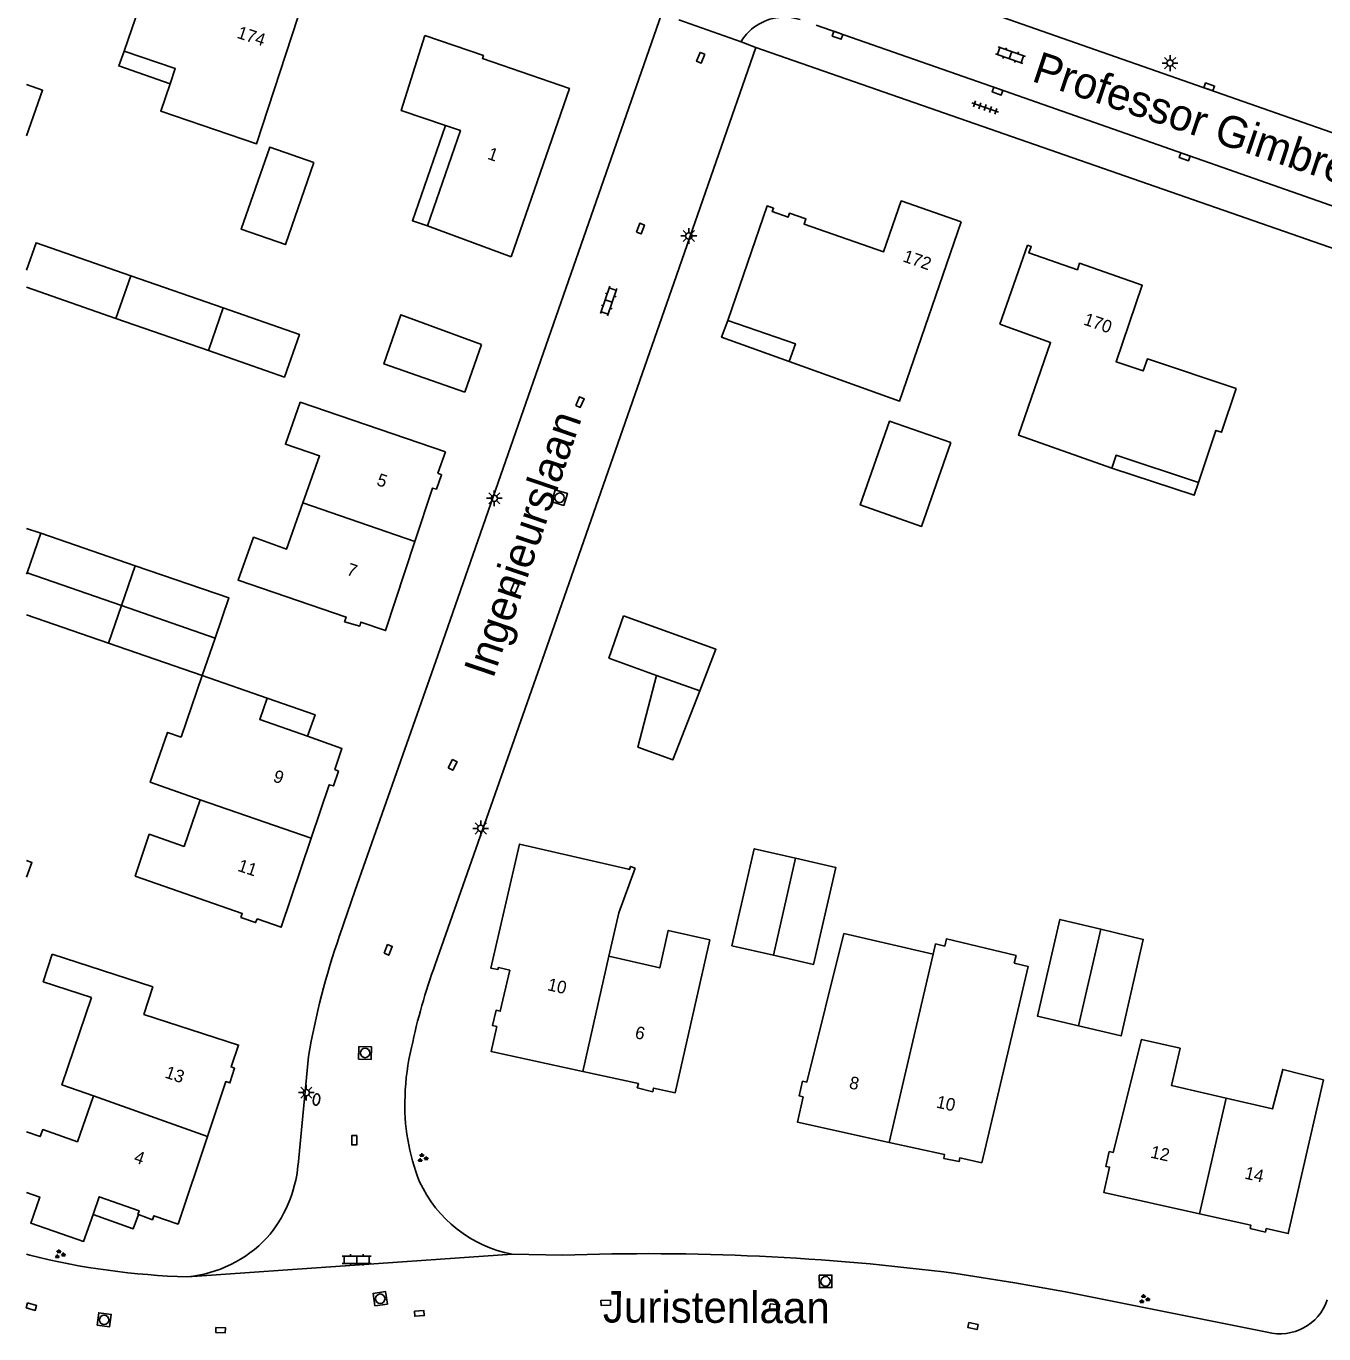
# Model space of a CAD drawing. Extents: x 131000 to 133014, y 396499 to 399001.
# Drawn here: x 131000 to 131103.1, y 396804.1 to 396908.1 of the extents above; entities that cross this region are included whole.
import ezdxf

# ---------------------------------------------------------------- set-up
doc = ezdxf.new("R2010")
doc.units = 0
for name, color, linetype in [('gg-anno-huisnummerreeks BGT', 7, 'Continuous'), ('gg-anno-openbare ruimte label', 7, 'Continuous'), ('gg-bbg-bijgebouw', 7, 'Continuous'), ('gg-bbg-gedigitaliseerde bebouwing', 7, 'Continuous'), ('gg-bbg-gedigitaliseerde bijgebouw', 7, 'Continuous'), ('gg-bbg-hoofdgebouw', 7, 'Continuous'), ('gg-bbg-luifel en loopbrug', 7, 'Continuous'), ('gg-bbg-tussenscheiding', 7, 'Continuous'), ('gg-knt-verharding', 7, 'Continuous'), ('gt-grn-weggrens', 7, 'Continuous'), ('gt-symb-brandkraan', 7, 'Continuous'), ('gt-symb-groenvak', 7, 'Continuous'), ('gt-symb-klinker verharding', 7, 'Continuous'), ('gt-symb-kolk', 7, 'Continuous'), ('gt-symb-kolk center center', 7, 'Continuous'), ('gt-symb-lichtmast', 7, 'Continuous'), ('gt-symb-rioolschacht', 7, 'Continuous'), ('gt-symb-tegel verharding', 7, 'Continuous')]:
    doc.layers.add(name, color=color, linetype=linetype)

# ---------------------------------------------------------------- blocks, each defined once
blk = doc.blocks.new('gt0-KOLK')
at = {"layer": 'gt-symb-kolk'}
blk.add_lwpolyline([(0, 0), (0.38, 0), (0.38, 0.4), (-0.38, 0.4), (-0.38, 0), (0, 0)], dxfattribs=at)
blk = doc.blocks.new('gt0-TEG1')
at = {"layer": 'gt-symb-tegel verharding'}
for p, q in [((-1.12, 0), (1.12, 0)), ((-0.9, -0.25), (-0.9, 0.25)), ((-0.45, -0.25), (-0.45, 0.25)), ((0, -0.25), (0, 0.25)), ((0.45, -0.25), (0.45, 0.25)), ((0.9, -0.25), (0.9, 0.25))]:
    blk.add_line(p, q, dxfattribs=at)
blk = doc.blocks.new('gt0-LMAST')
at = {"layer": 'gt-symb-lichtmast'}
for p, q in [((-0.18, 0.17), (-0.45, 0.44)), ((-0.01, 0.25), (-0.01, 0.62)), ((0.17, 0.17), (0.44, 0.44)), ((-0.26, 0), (-0.63, 0)), ((-0.18, -0.18), (-0.45, -0.45)), ((-0.01, -0.25), (-0.01, -0.63)), ((0.44, -0.45), (0.17, -0.18)), ((0.24, 0), (0.62, 0))]:
    blk.add_line(p, q, dxfattribs=at)
blk.add_circle((-0.01, 0), 0.25, dxfattribs=at)
blk = doc.blocks.new('gt0-KL1')
at = {"layer": 'gt-symb-klinker verharding'}
for p, q in [((-1.15, 0.3), (1.15, 0.3)), ((-1, -0.3), (-1, 0.3)), ((-0.5, 0.3), (-0.5, 0.45)), ((0, -0.3), (0, 0.3)), ((0.5, 0.3), (0.5, 0.45)), ((1, -0.3), (1, 0.3)), ((-1.15, -0.3), (1.15, -0.3)), ((-0.5, -0.45), (-0.5, -0.3)), ((0.5, -0.45), (0.5, -0.3))]:
    blk.add_line(p, q, dxfattribs=at)
blk = doc.blocks.new('gt0-KOLKCC')
at = {"layer": 'gt-symb-kolk center center'}
blk.add_lwpolyline([(-0.37, 0.2), (0.38, 0.2), (0.38, -0.2), (-0.37, -0.2)], close=True, dxfattribs=at)
blk = doc.blocks.new('gt0-RS')
at = {"layer": 'gt-symb-rioolschacht'}
blk.add_lwpolyline([(-0.5, -0.5), (0.5, -0.5), (0.5, 0.5), (-0.5, 0.5)], close=True, dxfattribs=at)
blk.add_circle((0, 0), 0.375, dxfattribs=at)
blk = doc.blocks.new('gt0-GRVAK')
at = {"layer": 'gt-symb-groenvak'}
for p, q in [((-0.11, 0.19), (-0.23, 0.24)), ((-0.18, 0.15), (0.09, 0.15)), ((-0.09, 0.21), (-0.16, 0.32)), ((-0.05, 0.21), (-0.05, 0.39)), ((0, 0.21), (0.06, 0.32)), ((0.02, 0.19), (0.13, 0.24)), ((0.26, -0.05), (0.2, 0.06)), ((0.3, -0.05), (0.3, 0.13)), ((0.35, -0.05), (0.41, 0.06)), ((-0.24, -0.23), (-0.36, -0.18)), ((-0.32, -0.26), (-0.05, -0.26)), ((-0.23, -0.21), (-0.29, -0.09)), ((-0.18, -0.2), (-0.18, -0.02)), ((-0.14, -0.21), (-0.07, -0.09)), ((-0.12, -0.23), (0, -0.18)), ((0.24, -0.07), (0.12, -0.02)), ((0.17, -0.11), (0.44, -0.11)), ((0.37, -0.07), (0.49, -0.02))]:
    blk.add_line(p, q, dxfattribs=at)
blk = doc.blocks.new('gt0-BR')
at = {"layer": 'gt-symb-brandkraan'}
for centre, radius, start, end in [((-0.24, 0), 0.206, 107.5669, 252.4331), ((0.6, -2.66), 3, 106.892, 107.5669), ((0, -0.69), 0.938, 73.108, 106.892), ((-0.6, -2.66), 3, 72.4331, 73.108), ((0.24, 0), 0.206, 287.567, 72.4331), ((0.6, 2.66), 3, 252.4331, 253.108), ((0, 0.69), 0.938, 253.108, 286.8921), ((-0.6, 2.66), 3, 286.8921, 287.567)]:
    blk.add_arc(centre, radius, start, end, dxfattribs=at)

msp = doc.modelspace()

# ---------------------------------------------------------------- linework, layer by layer
at = {"layer": 'gg-bbg-bijgebouw'}
for p, q in [((131036.15, 396882.77), (131034.81, 396879)), ((131047.42, 396861.2), (131046.26, 396857.84))]:
    msp.add_line(p, q, dxfattribs=at)
at = {"layer": 'gg-bbg-gedigitaliseerde bebouwing'}
for p, q in [((131007.74, 396906.1), (131010.7, 396914.65)), ((131038.5, 396889.73), (131031.84, 396892.2)), ((131077.32, 396884.39), (131079.51, 396890.68)), ((131013.95, 396856.47), (131012.27, 396851.58)), ((131075.9, 396817.74), (131078.76, 396829.85)), ((131005.29, 396822.99), (131005.31, 396823.06))]:
    msp.add_line(p, q, dxfattribs=at)
for points in [[(131022.01, 396910.13), (131018.27, 396898.73), (131010.66, 396901.33), (131011.4, 396903.49)], [(131033.27, 396900.19), (131029.76, 396901.36), (131031.64, 396907.33)], [(131011.4, 396903.49), (131011.81, 396904.7), (131007.74, 396906.1)], [(131031.84, 396892.2), (131034.46, 396899.79), (131033.27, 396900.19)], [(131074.24, 396892.53), (131069.36, 396878.28), (131060.59, 396881.42)], [(131086.23, 396872.95), (131078.79, 396875.57), (131081.35, 396882.94), (131077.32, 396884.39)], [(131096.1, 396879.27), (131094.93, 396875.8), (131094.48, 396875.95), (131093.1, 396871.82)], [(131021.96, 396870.2), (131023.28, 396873.92), (131020.56, 396874.85), (131021.74, 396878.18), (131033.27, 396874.24)], [(131093.1, 396871.82), (131086.56, 396873.97), (131086.23, 396872.95)], [(131021.96, 396870.2), (131020.66, 396866.51), (131018.03, 396867.45), (131016.8, 396864.05), (131025.38, 396861.11), (131025.27, 396860.73)], [(131013.8, 396846.6), (131009.82, 396847.98), (131011.2, 396851.95), (131012.27, 396851.58)], [(131013.8, 396846.6), (131012.51, 396842.89), (131009.75, 396843.85), (131008.63, 396840.53), (131017.14, 396837.55), (131017.03, 396837.24)], [(131046.25, 396834.16), (131047.04, 396837.62), (131048.34, 396841.17)], [(131051.54, 396823.31), (131054.27, 396835.46), (131050.98, 396836.21), (131050.3, 396833.23), (131046.25, 396834.16)], [(131072.02, 396834.32), (131064.93, 396835.96), (131061.98, 396824.15), (131061.65, 396824.23)], [(131078.76, 396829.85), (131079.58, 396833.34), (131078.46, 396833.61), (131078.61, 396834.22), (131073.08, 396835.53), (131072.94, 396834.97), (131072.21, 396835.14), (131072.02, 396834.32)], [(131005.16, 396830.89), (131001.33, 396832.13), (131002.04, 396834.32)], [(131005.16, 396830.89), (131002.81, 396823.95), (131005.31, 396823.06)], [(131095.29, 396822.88), (131090.96, 396823.88), (131091.64, 396826.84), (131088.57, 396827.53), (131086.33, 396818.56), (131086.01, 396818.64)], [(131103.02, 396824.33), (131099.79, 396825.16), (131098.98, 396822.02), (131095.29, 396822.88)]]:
    msp.add_lwpolyline(points, dxfattribs=at)
at = {"layer": 'gg-bbg-gedigitaliseerde bijgebouw'}
for p, q in [((131008.29, 396888.23), (131015.62, 396885.68)), ((131000, 396887.32), (131007.1, 396884.85)), ((131014.44, 396882.29), (131015.62, 396885.68)), ((131014.44, 396882.29), (131007.1, 396884.85)), ((131000, 396868.16), (131001.14, 396867.77)), ((131001.14, 396867.77), (131008.62, 396865.19)), ((131007.53, 396862.02), (131008.62, 396865.19)), ((131000, 396861.28), (131006.51, 396859.04)), ((131006.51, 396859.04), (131007.53, 396862.02)), ((131050.04, 396856.48), (131046.26, 396857.84)), ((131053.49, 396855.24), (131050.04, 396856.48))]:
    msp.add_line(p, q, dxfattribs=at)
for points in [[(131000, 396903.43), (131001.27, 396902.98), (131000, 396899.37)], [(131022.83, 396897.25), (131019.33, 396898.46), (131017.06, 396891.93), (131020.56, 396890.72), (131022.83, 396897.25)], [(131000, 396888.69), (131000.76, 396890.86), (131008.29, 396888.23)], [(131034.81, 396879), (131028.39, 396881.23), (131029.74, 396885.14), (131036.15, 396882.77)], [(131073.42, 396874.98), (131068.55, 396876.68), (131066.23, 396870.02), (131071.1, 396868.32), (131073.42, 396874.98)], [(131047.42, 396861.2), (131054.76, 396858.56), (131053.49, 396855.24)], [(131061.09, 396841.95), (131057.81, 396842.7), (131056.04, 396834.99), (131059.35, 396834.23)], [(131000, 396841.76), (131000.42, 396841.61), (131000, 396840.43)], [(131059.35, 396834.23), (131062.52, 396833.51), (131064.28, 396841.22), (131061.09, 396841.95)], [(131085.34, 396836.3), (131082.09, 396837.09), (131080.32, 396829.39), (131083.56, 396828.62)], [(131083.56, 396828.62), (131086.95, 396827.82), (131088.72, 396835.49), (131085.34, 396836.3)]]:
    msp.add_lwpolyline(points, dxfattribs=at)
at = {"layer": 'gg-bbg-hoofdgebouw'}
msp.add_line((131013.95, 396856.47), (131019.12, 396854.67), dxfattribs=at)
for points in [[(131038.5, 396889.73), (131043.12, 396903.13), (131036.22, 396905.51), (131036.3, 396905.74), (131031.64, 396907.33)], [(131074.24, 396892.53), (131069.49, 396894.18), (131068.09, 396890.14), (131061.77, 396892.34), (131061.92, 396892.75), (131060.61, 396893.2), (131060.51, 396892.9), (131059.24, 396893.34), (131059.34, 396893.61), (131058.83, 396893.79), (131055.7, 396884.69)], [(131096.1, 396879.27), (131089.04, 396881.63), (131088.7, 396880.67), (131086.55, 396881.41), (131088.64, 396887.49), (131083.66, 396889.23), (131083.48, 396888.72), (131079.63, 396890.06), (131079.81, 396890.57), (131079.51, 396890.68)], [(131055.7, 396884.69), (131061.08, 396882.84), (131060.59, 396881.42)], [(131030.84, 396867.11), (131032.24, 396871.37), (131032.56, 396871.28), (131032.97, 396872.43), (131032.68, 396872.55), (131033.27, 396874.24)], [(131025.27, 396860.73), (131026.47, 396860.4), (131026.55, 396860.71), (131028.52, 396860.04), (131030.84, 396867.11)], [(131019.12, 396854.67), (131018.52, 396852.97), (131022.32, 396851.64)], [(131022.32, 396851.64), (131025.05, 396850.68), (131024.49, 396848.99), (131024.78, 396848.86), (131024.38, 396847.69), (131024.04, 396847.79), (131022.61, 396843.55)], [(131017.03, 396837.24), (131018.19, 396836.83), (131018.32, 396837.13), (131020.23, 396836.46), (131022.61, 396843.55)], [(131044.19, 396825), (131036.9, 396826.59), (131037.35, 396828.57), (131037.01, 396828.65), (131037.3, 396829.87), (131037.63, 396829.79), (131038.38, 396833.05), (131037.48, 396833.26), (131037.44, 396833.11), (131036.88, 396833.22), (131039.17, 396843.07), (131047.82, 396841.08)], [(131048.34, 396841.17), (131047.97, 396841.3), (131047.91, 396841.06), (131047.82, 396841.08)], [(131002.04, 396834.32), (131010.03, 396831.72), (131009.32, 396829.54), (131016.84, 396827.09), (131016.25, 396825.36), (131016.53, 396825.25), (131016.15, 396824.09), (131015.83, 396824.19), (131014.37, 396819.83)], [(131051.54, 396823.31), (131049.81, 396823.68), (131049.74, 396823.39), (131048.52, 396823.7), (131048.61, 396824.04), (131044.19, 396825)], [(131068.54, 396819.36), (131061.24, 396820.98), (131061.69, 396822.98), (131061.38, 396823.05), (131061.65, 396824.23)], [(131103.02, 396824.33), (131100.23, 396812.11), (131098.48, 396812.51), (131098.42, 396812.24), (131097.21, 396812.52), (131097.27, 396812.78), (131093.19, 396813.69)], [(131000, 396820.21), (131001.09, 396819.83), (131001.28, 396820.38), (131004.04, 396819.42), (131005.29, 396822.99)], [(131014.37, 396819.83), (131012.03, 396812.87), (131010.1, 396813.53), (131010, 396813.22), (131008.88, 396813.62)], [(131075.9, 396817.74), (131074.14, 396818.13), (131074.08, 396817.84), (131072.86, 396818.09), (131072.93, 396818.39), (131068.54, 396819.36)], [(131093.19, 396813.69), (131085.59, 396815.38), (131086.04, 396817.39), (131085.73, 396817.46), (131086.01, 396818.64)], [(131000, 396815.37), (131001.05, 396815.01), (131000.33, 396812.95), (131004.53, 396811.49), (131005.28, 396813.62)], [(131005.28, 396813.62), (131005.77, 396815.04), (131008.94, 396813.93), (131008.84, 396813.63), (131008.88, 396813.62)]]:
    msp.add_lwpolyline(points, dxfattribs=at)
at = {"layer": 'gg-bbg-luifel en loopbrug'}
for p, q in [((131007.53, 396862.02), (131014.97, 396859.43)), ((131013.95, 396856.47), (131014.97, 396859.43)), ((131006.51, 396859.04), (131013.95, 396856.47))]:
    msp.add_line(p, q, dxfattribs=at)
for points in [[(131007.74, 396906.1), (131007.32, 396904.91), (131011.4, 396903.49)], [(131031.84, 396892.2), (131030.65, 396892.61), (131033.27, 396900.19)], [(131015.62, 396885.68), (131021.67, 396883.57), (131020.49, 396880.19), (131014.44, 396882.29)], [(131055.7, 396884.69), (131055.22, 396883.35), (131060.59, 396881.42)], [(131086.23, 396872.95), (131092.76, 396870.8), (131093.1, 396871.82)], [(131008.62, 396865.19), (131016.07, 396862.63), (131014.97, 396859.43)], [(131053.49, 396855.24), (131051.35, 396849.77), (131048.57, 396850.77), (131050.04, 396856.48)], [(131019.12, 396854.67), (131022.92, 396853.35), (131022.32, 396851.64)], [(131005.28, 396813.62), (131008.48, 396812.5), (131008.88, 396813.62)]]:
    msp.add_lwpolyline(points, dxfattribs=at)
at = {"layer": 'gg-bbg-tussenscheiding'}
for p, q in [((131007.1, 396884.85), (131008.29, 396888.23)), ((131030.84, 396867.11), (131021.96, 396870.2)), ((131000.04, 396864.63), (131001.14, 396867.77)), ((131000, 396864.65), (131000.04, 396864.63)), ((131000, 396864.51), (131000.04, 396864.63)), ((131000.04, 396864.63), (131007.53, 396862.02)), ((131022.61, 396843.55), (131013.8, 396846.6)), ((131061.09, 396841.95), (131059.35, 396834.23)), ((131085.34, 396836.3), (131083.56, 396828.62)), ((131046.25, 396834.16), (131044.19, 396825)), ((131072.02, 396834.32), (131068.54, 396819.36)), ((131005.31, 396823.06), (131014.37, 396819.83)), ((131095.29, 396822.88), (131093.19, 396813.69))]:
    msp.add_line(p, q, dxfattribs=at)
at = {"layer": 'gg-knt-verharding'}
for p, q in [((131057.93, 396906.39), (131056.76, 396906.83)), ((131021.57, 396817.57), (131022.39, 396826.18)), ((131000, 396810.47), (131000.26, 396810.39)), ((131038.57, 396810.48), (131042.58, 396810.41))]:
    msp.add_line(p, q, dxfattribs=at)
for points in [[(131064.53, 396913.34), (131066.31, 396912.74), (131109.45, 396897.6), (131125.49, 396891.95)], [(131050.45, 396909.03), (131032.67, 396858.06), (131026.11, 396839.41), (131024.87, 396835.79)], [(131196.34, 396861.29), (131193.8, 396862.19), (131161.43, 396873.55), (131142.49, 396880.22), (131124.14, 396886.61), (131107.63, 396892.43), (131077.21, 396903.1), (131062.73, 396908.15)], [(131032.47, 396833.5), (131040.97, 396857.68), (131051.64, 396888.26), (131057.93, 396906.39)], [(131057.93, 396906.39), (131178.97, 396864.24), (131198.34, 396857.4)], [(131073.83, 396808.95), (131078.51, 396808.2), (131082.54, 396807.48), (131098.56, 396804.28)]]:
    msp.add_lwpolyline(points, dxfattribs=at)
for centre, radius, start, end in [((131060.57, 396904.5), 4.47, 129.1494, 148.6284), ((131060.22, 396904.73), 4.06, 72.3488, 127.3042), ((131084.06, 396815.4), 62.61, 160.9896, 170.081), ((131075.67, 396817.58), 46.04, 159.7671, 168.3099), ((131048.63, 396822.53), 18.57, 166.3629, 178.3777), ((131046.34, 396822.31), 16.29, 177.3867, 201.8761), ((131011.46, 396818.46), 10.14, 318.7494, 354.9394), ((131040.51, 396820.51), 10.22, 204.7093, 259.0466), ((131011.83, 396818.58), 9.95, 275.521, 316.8573), ((131014.51, 396867.98), 59.33, 256.0971, 268.3346), ((131049.21, 396616.99), 193.53, 82.6912, 91.9623), ((131099.58, 396808.1), 3.95, 255.0499, 341.5272)]:
    msp.add_arc(centre, radius, start, end, dxfattribs=at)
at = {"layer": 'gt-grn-weggrens'}
for p, q in [((131051.81, 396908.58), (131056.76, 396906.83)), ((131038.57, 396810.48), (131012.79, 396808.68))]:
    msp.add_line(p, q, dxfattribs=at)

# ---------------------------------------------------------------- block references
at = {"layer": 'gt-symb-brandkraan', "rotation": 81.19719554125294}
msp.add_blockref('gt0-BR', (131023.03, 396822.77), dxfattribs=at)
at = {"layer": 'gt-symb-groenvak'}
for p in [(131031.45, 396818.12), (131002.62, 396810.47), (131088.78, 396806.91)]:
    msp.add_blockref('gt0-GRVAK', p, dxfattribs=at)
at = {"layer": 'gt-symb-klinker verharding'}
for p, rotation in [((131078.17, 396905.77), -19.214311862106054), ((131046.25, 396886.23), 71.14816421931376)]:
    msp.add_blockref('gt0-KL1', p, dxfattribs=dict(at, rotation=rotation))
msp.add_blockref('gt0-KL1', (131026.23, 396810.03), dxfattribs=at)
at = {"layer": 'gt-symb-kolk'}
for p, rotation in [((131064.5, 396907.54), 160.78568813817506), ((131077.21, 396903.1), 160.6775176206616), ((131093.89, 396903.06), -19.39552831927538), ((131092.07, 396897.88), 160.6775176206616)]:
    msp.add_blockref('gt0-KOLK', p, dxfattribs=dict(at, rotation=rotation))
at = {"layer": 'gt-symb-kolk center center'}
for p, rotation in [((131053.56, 396905.57), -111.71629047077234), ((131048.77, 396891.98), 70.55043123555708), ((131043.96, 396878.19), 65.79315601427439), ((131038.78, 396863.42), 68.10284941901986), ((131033.85, 396849.36), 63.12746100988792), ((131028.72, 396834.66), 68.10284941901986), ((131026.04, 396819.54), -90.57293869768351), ((131000.38, 396806.31), -15.969016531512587), ((131046.02, 396806.62), -178.39613722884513), ((131059.42, 396806.3), -5.391463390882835), ((131031.2, 396805.77), 3.6120749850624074), ((131075.18, 396804.77), -12.827123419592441), ((131015.41, 396804.44), -0.802088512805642)]:
    msp.add_blockref('gt0-KOLKCC', p, dxfattribs=dict(at, rotation=rotation))
at = {"layer": 'gt-symb-lichtmast'}
for p in [(131090.85, 396905.14), (131052.62, 396891.4), (131037.17, 396870.55), (131036.09, 396844.32), (131022.23, 396823.32)]:
    msp.add_blockref('gt0-LMAST', p, dxfattribs=at)
at = {"layer": 'gt-symb-rioolschacht'}
for p, rotation in [((131042.34, 396870.6), -106.31519324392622), ((131026.89, 396826.47), -90.97393443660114), ((131063.48, 396808.32), -89.71352348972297), ((131028.1, 396806.94), 8.454261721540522), ((131006.16, 396805.26), -7.992313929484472)]:
    msp.add_blockref('gt0-RS', p, dxfattribs=dict(at, rotation=rotation))
at = {"layer": 'gt-symb-tegel verharding', "rotation": -19.21431186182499}
msp.add_blockref('gt0-TEG1', (131076.16, 396901.6), dxfattribs=at)

# ---------------------------------------------------------------- texts
at = {"layer": 'gg-anno-huisnummerreeks BGT'}
for s, rotation, p in [('174', 341.8, (131016.65, 396907.16)), ('1', 341, (131036.55, 396897.54)), ('172', 340.9, (131069.55, 396889.39)), ('170', 340.7, (131083.9, 396884.38)), ('5', 341.2, (131027.74, 396871.62)), ('7', 341.8, (131025.36, 396864.49)), ('9', 341.1, (131019.52, 396848.06)), ('11', 341.4, (131016.7, 396840.96)), ('10', 347.1, (131041.32, 396831.47)), ('6', 347, (131048.27, 396827.66)), ('13', 341.2, (131010.92, 396824.53)), ('8', 347.5, (131065.29, 396823.67)), ('10', 347.6, (131072.21, 396822.14)), ('4', 340.7, (131008.46, 396817.81)), ('12', 347.5, (131089.23, 396818.16)), ('14', 347.4, (131096.71, 396816.49))]:
    msp.add_text(s, height=1, rotation=rotation, dxfattribs=at).set_placement(p)
at = {"layer": 'gg-anno-openbare ruimte label'}
for s, rotation, p in [('Professor Gimbrèrelaan', 341.5, (131079.76, 396903.73)), ('Ingenieurslaan', 71.2, (131037.06, 396856.15)), ('Juristenlaan', 359.8, (131045.78, 396805.05))]:
    msp.add_text(s, height=2.5, rotation=rotation, dxfattribs=at).set_placement(p)

doc.saveas('drawing.dxf')
